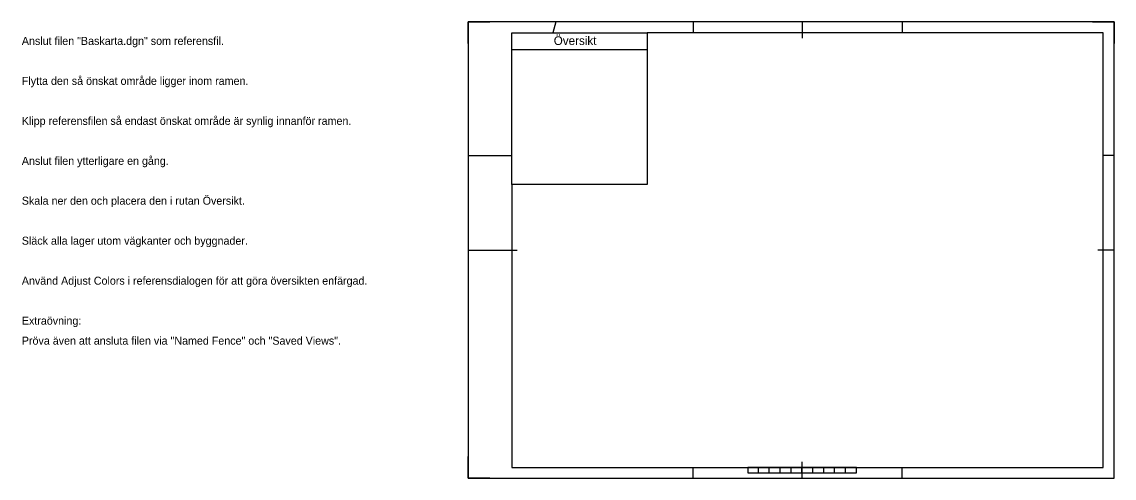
# Model space of a CAD drawing. Extents: x 76712 to 77717, y 9031 to 9451.
import ezdxf

# ---------------------------------------------------------------- set-up
doc = ezdxf.new("R2010")
doc.units = 0
doc.layers.add('Instruktioner', color=7, linetype='Continuous')
doc.layers.add('Plotshape', color=7, linetype='Continuous')

msp = doc.modelspace()

# ---------------------------------------------------------------- linework, layer by layer
at = {"layer": 'Instruktioner'}
for p, q in [((77122.7, 9431), (77122.7, 9451)), ((77122.7, 9451), (77142.7, 9451)), ((77203.3, 9451), (77200.6, 9441)), ((77329.7, 9451), (77329.7, 9441)), ((77429.7, 9451), (77429.7, 9436)), ((77521.7, 9451), (77521.7, 9441)), ((77696.7, 9451), (77716.7, 9451)), ((77716.7, 9451), (77716.7, 9431)), ((77162.7, 9425.7), (77287.2, 9425.7)), ((77122.7, 9328), (77162.7, 9328)), ((77716.7, 9328), (77706.7, 9328)), ((77122.7, 9241), (77167.7, 9241)), ((77716.7, 9241), (77701.7, 9241)), ((77122.7, 9031), (77122.7, 9051)), ((77716.7, 9031), (77716.7, 9051)), ((77329.7, 9031), (77329.7, 9041)), ((77389.6, 9036), (77389.6, 9041)), ((77399.6, 9036), (77399.6, 9041)), ((77409.6, 9036), (77409.6, 9041)), ((77419.6, 9036), (77419.6, 9041)), ((77429.6, 9036), (77429.6, 9041)), ((77429.7, 9031), (77429.7, 9046)), ((77439.6, 9036), (77439.6, 9041)), ((77449.6, 9036), (77449.6, 9041)), ((77459.6, 9036), (77459.6, 9041)), ((77469.6, 9036), (77469.6, 9041)), ((77521.7, 9031), (77521.7, 9041)), ((77142.7, 9031), (77122.7, 9031)), ((77696.7, 9031), (77716.7, 9031))]:
    msp.add_line(p, q, dxfattribs=at)
for points in [[(77162.7, 9441), (77287.2, 9441), (77287.2, 9301.3), (77162.7, 9301.3)], [(77162.7, 9301.3), (77162.7, 9041), (77706.7, 9041), (77706.7, 9441), (77287.2, 9441), (77287.2, 9301.3)], [(77379.7, 9036), (77479.7, 9036), (77479.7, 9041), (77379.7, 9041)]]:
    msp.add_lwpolyline(points, close=True, dxfattribs=at)
at = {"layer": 'Plotshape'}
msp.add_lwpolyline([(77122.7, 9031), (77716.7, 9031), (77716.7, 9451), (77122.7, 9451)], close=True, dxfattribs=at)

# ---------------------------------------------------------------- texts
at = {"layer": 'Instruktioner'}
for s, height, p in [('Anslut filen "Baskarta.dgn" som referensfil.', 7.358, (76712.3, 9429.8)), ('Översikt', 8, (77201.4, 9429.7)), ('Flytta den så önskat område ligger inom ramen.', 7.358, (76712.3, 9393)), ('Klipp referensfilen så endast önskat område är synlig innanför ramen.', 7.358, (76712.3, 9356.2)), ('Anslut filen ytterligare en gång.', 7.358, (76712.3, 9319.4)), ('Skala ner den och placera den i rutan Översikt.', 7.358, (76712.3, 9282.7)), ('Släck alla lager utom vägkanter och byggnader.', 7.358, (76712.3, 9245.9)), ('Använd Adjust Colors i referensdialogen för att göra översikten enfärgad.', 7.358, (76712.3, 9209.1)), ('Extraövning:', 7.358, (76712.3, 9172.3)), ('Pröva även att ansluta filen via "Named Fence" och "Saved Views".', 7.358, (76712.3, 9153.9))]:
    msp.add_text(s, height=height, dxfattribs=at).set_placement(p)

doc.saveas('drawing.dxf')
